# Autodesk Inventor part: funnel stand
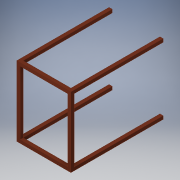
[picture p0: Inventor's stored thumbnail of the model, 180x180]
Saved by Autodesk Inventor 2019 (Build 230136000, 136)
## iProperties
Created: 2021-07
Part Number: funnel stand
Material: Copper, Alloy
Document SubType Name: Modeling
Designer: Avinash
Density: 8.92 g/cm^3
Appearance: Copper - Satin
Author: Avinash
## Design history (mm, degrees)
sketch "Sketch1"
  geometry: L1 (0, 0)-(-150, 0); L2 (-150, 0)-(-150, 200); L3 (-150, 200)-(0, 200); L4 (0, 200)-(0, 0); L5 (10, 210)-(-160, 210); L6 (-160, 210)-(-160, -10); L7 (-160, -10)-(10, -10); L8 (10, -10)-(10, 210)
  constraints: 16 end point, 2 parallel, 1 horizontal, 1 perpendicular
  dimensions: "d0" = 150 distance of L2.end L3.end; "d1" = 200 distance of L3.end L1.start
extrude "Extrusion3" new body sketch "Sketch1" distance "d6" = 10; taper "d7" = 0 deg
sketch "Sketch3"
  geometry: L1 (-10, -10)-(-10, 210) reference; L2 (0, 0)-(-10, 0); L3 (-10, 0)-(-10, -10); L4 (-10, -10)-(0, -10); L5 (0, -10)-(0, 0); L6 (0, 200)-(150, 200) reference; L7 (-10, 210)-(160, 210) reference; L8 (0, 200)-(-10, 200); L9 (-10, 200)-(-10, 210); L10 (-10, 210)-(0, 210); L11 (0, 210)-(0, 200); L12 (150, 0)-(150, 200) reference; L13 (160, 210)-(150, 210); L14 (150, 210)-(150, 200); L15 (150, 200)-(160, 200); L16 (160, 200)-(160, 210); L17 (160, -10)-(-10, -10) reference; L18 (160, -10)-(150, -10); L19 (150, -10)-(150, 0); L20 (150, 0)-(160, 0); L21 (160, 0)-(160, -10)
  constraints: 32 end point, 8 parallel, 4 horizontal, 4 perpendicular
extrude "Extrusion4" join sketch "Sketch3" distance "d8" = 280; taper "d9" = 0 deg
body "Solid2"
